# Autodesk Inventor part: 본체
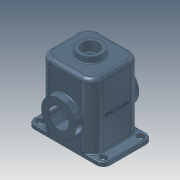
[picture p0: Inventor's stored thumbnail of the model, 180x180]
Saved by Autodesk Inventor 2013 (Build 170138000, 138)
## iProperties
Company: 한국ATC센터
Created: 2014-10
Part Number: 본체
Document SubType Name: Modeling
Designer: 한국ATC센터
Density: 1 g/cm^3
Material: 일반
Mass: 1212.35 g
Surface Area: 2358.49 cm^2
Volume: 1212.35 cm^3
Author: KYOUNG IL JANG
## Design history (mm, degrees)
sketch "스케치1"
  geometry: L1 (-70, 65)-(70, 65); L2 (70, 65)-(70, -65); L3 (70, -65)-(-70, -65); L4 (-70, -65)-(-70, 65); 3 further points
  constraints: 8 end point, 2 midpoint, 2 parallel, 1 horizontal, 1 horizontal alignment, 1 perpendicular, 1 vertical alignment
  dimensions: "d0" = 140 distance of L2.end L3.end; "d68" = 130 distance of L3.end L1.start
extrude "돌출1" new body sketch "스케치1" distance "d1" = 180; taper "d2" = 0 deg
fillet "모깎기1" dims "d3" = 20
feature "쉘1" dims "d4" = 10
sketch "스케치2"
  geometry: L1 (-70, 45)-(-70, -45) reference; L2 (-50, -65)-(-82, -65); L3 (-82, 65)-(-50, 65); L4 (-85, 57)-(-82, 57); L5 (-82, 41)-(-85, 41); L6 (-100, 47)-(-100, -47); A1 r 20 centre (-50, 45) between (-50, 65) and (-70, 45) reference; A2 r 20 centre (-50, -45) between (-70, -45) and (-50, -65) reference; A3 r 8 centre (-82, 49) between (-82, 41) and (-82, 57); A4 r 8 centre (-85, 49) between (-85, 57) and (-85, 41); A5 r 18 centre (-82, 47) between (-82, 65) and (-100, 47); A6 r 18 centre (-82, -47) between (-100, -47) and (-82, -65); 1 further point
  constraints: 10 end point, 9 tangent, 8 point on circle, 4 centre point, 2 parallel, 2 perpendicular, 1 equal radius
  dimensions: "d6" = 49 vertical distance of point (0, 0) A3.centre; "d8" = 16 distance between parallel lines of L4 L5; "d64" = 18 radius of A5; "d65" = 12 distance from line of A3.centre L1; "d66" = 30 distance between parallel lines of L6 L1; "d67" = 3 distance of A4.centre A3.centre
extrude "돌출2" join sketch "스케치2" distance "d9" = 10; taper "d10" = 0 deg
extrude "돌출3" cut sketch "스케치2" stored distance "d11" = 10; taper "d12" = 0 deg
sketch "스케치3"
  geometry: L1 (-65, 0)-(-65, 180) reference; L2 (-55, 0)-(-55, 170) reference; L3 (-83, 75)-(-51, 75); L4 (45, 0)-(-45, 0) reference; L5 (-83, 75)-(-83, 120.5); L6 (-83, 120.5)-(-55, 120.5); L7 (-55, 120.5)-(-51, 116.5); L8 (-51, 116.5)-(-51, 75); 2 further points
  constraints: 10 end point, 4 perpendicular, 1 point on line
  dimensions: "d13" = 75 distance between parallel lines of L3 L4; "d14" = 18 distance from line of L1 L3.start; "d15" = 4 distance from line of L3.end L2; "d16" = 91 diameter of L6 L3; "d17" = 135 deg angle of L7 L2
revolve "회전1" sketch "스케치3" stored, may be unused: angle "d18" = 90 deg
sketch "스케치4"
  geometry: C1 r 45.5 at (0, 0) reference; 2 further points
  constraints: 1 vertical alignment
  dimensions: "d19" = 35 distance of C1.centre point (0, 35)
hole "구멍1" sketch "스케치4" at (0, 35) diameter "d20" = 3.459; stored, may be unused: countersink angle "d24" = 90 deg, drill point angle "d26" = 118 deg; dims "d21" = 13, "d22" = 4, "d23" = 2, "d25" = 16
fillet "모깎기2" dims "d30" = 3
hole "구멍2" diameter "d33" = 52; stored, may be unused: countersink angle "d37" = 90 deg, drill point angle "d39" = 118 deg; dims "d31" = 10, "d32" = 10, "d34" = 13, "d35" = 4, "d36" = 2, "d38" = 16
sketch "스케치5"
  geometry: C1 r 31 at (0, 0); 1 further point
  constraints: 1 centre point, 1 coincident
  dimensions: "d40" = 62 diameter of C1
extrude "돌출4" join sketch "스케치5" distance "d41" = 15; taper "d42" = 0 deg
hole "구멍3" diameter "d45" = 43; stored, may be unused: countersink angle "d49" = 90 deg, drill point angle "d51" = 118 deg; dims "d43" = 10, "d44" = 10, "d46" = 13, "d47" = 4, "d48" = 2, "d50" = 16
fillet "모깎기3" dims "d52" = 3
fillet "모깎기4" dims "d53" = 3
chamfer "모따기1" distance "d55" = 1; stored, may be unused: second distance "d56" = 2, angle "d57" = 45 deg
sketch "스케치6"
  geometry: 2 further points
  constraints: 1 vertical alignment, 1 other
  dimensions: "d71" = 90 distance of point (0, 0) point (0, 90)
feature "엠보싱2" sketch "스케치6" dims "d0" = 140, "d68" = 130, "d72" = 1, "d73" = 0
fillet "모깎기6" dims "d74" = 10
sketch "스케치7"
  geometry: C1 r 15 at (0, 0); C2 r 21.5 at (0, 0) reference; C3 r 25 at (0, 0); 1 further point
  constraints: 2 centre point, 2 coincident
  dimensions: "d61" = 30 diameter of C1; "d75" = 50 diameter of C3
extrude "돌출5" join sketch "스케치7" distance "d62" = 10; taper "d63" = 0 deg
feature "면 이동1" dims "d76" = 1
fillet "모깎기7" dims "d77" = 3
node "솔리드1"
mirror "대칭1"
mirror "대칭2"
pattern_circular "원형 패턴1" dims angle "d28" = 360 deg
mirror "대칭3"
